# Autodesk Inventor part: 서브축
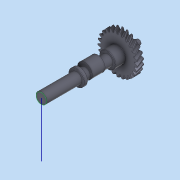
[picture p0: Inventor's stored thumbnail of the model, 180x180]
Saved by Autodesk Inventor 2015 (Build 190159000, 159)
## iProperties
Created: 2018-07
Part Number: 서브축
Material: 강철
Document SubType Name: Modeling
Designer: mduedu
Categories: <?xml version="1.0" encoding="UTF-16"?> <MemberInstance><Categories><FamilyTemplate><FamilyTemplateParameter ValueType="xs:double" Id="1" ObjectReferenceKey="da
Density: 7.85 g/cm^3
Mass: 513.764 g
Surface Area: 178.04 cm^2
Volume: 65.4477 cm^3
Appearance: 강철
Author: mduedu
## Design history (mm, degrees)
sketch "Sketch1"
  geometry: C1 r 30.864 at (0, 0)
  constraints: 1 centre point
  dimensions: "d0" = 61.72879 diameter of C1 (= da_da)
extrude "Extrusion1" new body sketch "Sketch1" distance "d1" = 10 (= da_b); taper "d2" = 0 deg
workplane "Work Plane2"
sketch "Sketch2"
  geometry: C1 r 30.864 at (0, 0) reference; C2 r 29.013 at (0, 0)
  constraints: 1 centre point, 1 coincident
  dimensions: "d3" = 58.02632 diameter of C2 (= da_dw)
feature "피치 지름" sketch "Sketch2" dims "d4" = 10, "d5" = 0
workplane "Work Plane8"
workplane "Work Plane9"
feature "스퍼 기어" dims "da_b" = 10, "da_d" = 57.73503, "da_aw" = 44.1, "da_da" = 61.72879, "da_df" = 52.73503, "da_dw" = 58.02632, angle "da_beta" = 30 deg, "da_lefttooth" = 10, "da_righttooth" = 0
sketch "스케치3"
  geometry: C1 r 12.5 at (0, 0); 1 further point
  constraints: 1 centre point, 1 coincident
  dimensions: "d49" = 25 diameter of C1
extrude "돌출2" join sketch "스케치3" distance "d50" = 16; taper "d51" = 0 deg
sketch "스케치4"
  geometry: C1 r 8.5 at (0, 0); 1 further point
  constraints: 1 centre point, 1 coincident
  dimensions: "d52" = 17 diameter of C1
extrude "돌출3" join sketch "스케치4" distance "d53" = 103; taper "d54" = 0 deg
sketch "스케치5"
  geometry: C1 r 7.5 at (0, 0); 1 further point
  constraints: 1 centre point, 1 coincident
  dimensions: "d55" = 15 diameter of C1
extrude "돌출4" join sketch "스케치5" distance "d56" = 16; taper "d57" = 0 deg
sketch "스케치6"
  geometry: C1 r 4 at (0, 0); 1 further point
  constraints: 1 centre point, 1 coincident
  dimensions: "d58" = 8 diameter of C1
extrude "돌출5" join sketch "스케치6" distance "d59" = 7; taper "d60" = 0 deg
chamfer "모따기1" distance "d61" = 0.5; stored, may be unused: second distance "d62" = 2, angle "d63" = 45 deg
fillet "모깎기1" dims "d64" = 0.5
node "작업 평면11"
sketch "스케치7"
  geometry: C1 r 8.5 at (0, 0) reference; C2 r 11.5 at (0, -3); 1 further point
  constraints: 1 centre point, 1 tangent, 1 vertical alignment
  dimensions: "d66" = 23 diameter of C2; "d67" = 3 distance of point (0, 0) C2.centre (derived)
extrude "돌출6" join sketch "스케치7" stored distance "d68" = 20; taper "d69" = 0 deg
node "작업 평면12"
sketch "스케치8"
  geometry: C1 r 12.5 at (0, 0) reference; C2 r 12.5 at (0, 0) reference; 1 further point
extrude "돌출7" join sketch "스케치8" distance "d71" = 5; taper "d72" = 0 deg
chamfer "모따기2" distance "d73" = 0.5; stored, may be unused: second distance "d74" = 2, angle "d75" = 45 deg
sketch "스케치9"
  geometry: L1 (0, 0)-(0, 84.757); C1 r 8 at (0, 0) reference
  constraints: 2 end point, 1 vertical
body "Solid1"
body "Srf1"
node "투영된 루프1"
other parameters: "d16" = 44.1 (= da_aw), "d17" = 0, "d34" = 1.25664 (computed from da_z), "d39" = 0, "d41" = 0, "d43" = 44.1 (= da_aw), "d46" = 44.1 (= da_aw), "d47" = 0, "d48" = 0, "d65" = 25, "d70" = 48
